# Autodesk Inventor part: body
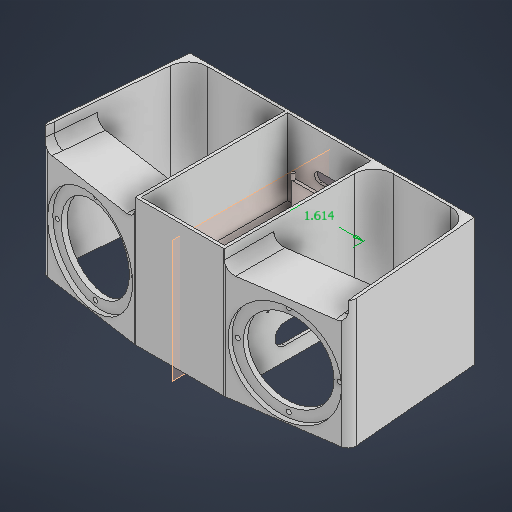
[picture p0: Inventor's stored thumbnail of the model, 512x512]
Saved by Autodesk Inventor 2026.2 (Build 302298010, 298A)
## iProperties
Created: 2026-08
Part Number: body
Material: Generic
Document SubType Name: Modeling
Designer: cpEwe
Density: 1 g/cm^3
Appearance: Default
Author: cpEwe
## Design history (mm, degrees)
sketch "Sketch1"
  geometry: L1 (-17.25, 41.25)-(17.25, 41.25); L2 (17.25, 41.25)-(17.25, -41.25); L3 (17.25, -41.25)-(-17.25, -41.25); L4 (-17.25, -41.25)-(-17.25, 41.25); L5 (-17.25, 41.25)-(17.25, -41.25); L6 (17.25, 41.25)-(-17.25, -41.25); C1 r 1 at (17.25, 41.25); C2 r 1 at (17.25, -41.25); C3 r 1 at (-17.25, -41.25); C4 r 1 at (-17.25, 41.25); 1 further point
  constraints: 12 end point, 4 centre point, 4 coincident, 3 equal radius, 2 midpoint, 2 parallel, 1 horizontal, 1 perpendicular
  dimensions: "d0" = 82.5 distance of L1.end L2.end; "d1" = 34.5 distance of L2.end L3.end; "d2" = 2 diameter of C1
extrude "Extrusion1" new body sketch "Sketch1" distance "d3" = 25; taper "d4" = 0 deg
sketch "Sketch2"
  geometry: L1 (0, 0)-(34.5, 0); L2 (34.5, 0)-(34.5, -82.5); L3 (34.5, -82.5)-(0, -82.5); L4 (36, -47.65)-(36, -82.65); L5 (36, -82.65)-(-1.5, -82.65); L6 (-1.5, -82.65)-(-1.5, -47.65); L7 (-1.5, -47.65)-(36, -47.65); L8 (36, -47.65)-(-1.5, -82.65); L9 (36, -82.65)-(-1.5, -47.65); L10 (0, -82.5)-(0, 0); C1 r 1 at (0, 0) reference; C2 r 1 at (34.5, -82.5) reference; C3 r 1 at (-1.5, -82.65); C4 r 1 at (-1.5, -47.65); C5 r 1 at (36, -47.65); C6 r 1 at (36, -82.65); 2 further points
  constraints: 20 end point, 4 centre point, 4 coincident, 3 equal radius, 3 parallel, 3 perpendicular, 2 midpoint, 1 horizontal
  dimensions: "d5" = 35 distance of L5.end L6.end; "d6" = 37.5 distance of L6.end L4.start; "d7" = 2 diameter of C3
extrude "Extrusion2" join sketch "Sketch2" distance "d8" = 7; taper "d9" = 0 deg
sketch "Sketch5"
  geometry: L1 (-9.75, 88.75)-(44.25, 88.75); L2 (44.25, 88.75)-(44.25, -6.25); L3 (44.25, -6.25)-(-9.75, -6.25); L4 (-9.75, -6.25)-(-9.75, 88.75); L5 (-9.75, 88.75)-(44.25, -6.25); L6 (44.25, 88.75)-(-9.75, -6.25); L7 (46.155, 90.655)-(-11.655, 90.655); L8 (-11.655, 90.655)-(-11.655, -8.155); L9 (-11.655, -8.155)-(46.155, -8.155); L10 (46.155, -8.155)-(46.155, 90.655); 1 further point
  constraints: 20 end point, 4 parallel, 2 midpoint, 2 perpendicular, 1 horizontal, 3 other
  dimensions: "d14" = 54 distance of L2.end L3.end; "d27" = 95 distance of L3.end L1.start; "d28" = 1.905 distance between parallel lines of L1 L7
extrude "Extrusion4" join sketch "Sketch5" stored distance "d16" = 2.54; taper "d17" = 0 deg
sketch "Sketch6"
  geometry: L1 (34.5, 0)-(0, 0); L2 (34.5, -1)-(0, -1); L3 (0, 1)-(34.5, 1); L4 (0, 82.5)-(34.5, 82.5); L5 (0, 83.5)-(34.5, 83.5); L6 (34.5, 81.5)-(0, 81.5); A1 r 1 centre (34.5, 0) between (34.5, -1) and (34.5, 1) reference; A2 r 1 centre (0, 0) between (0, -1) and (0, 1) reference; A3 r 1 centre (34.5, 0) between (34.5, -1) and (34.5, 1); A4 r 1 centre (0, 0) between (0, 1) and (0, -1); A5 r 1 centre (0, 82.5) between (0, 83.5) and (0, 81.5) reference; A6 r 1 centre (34.5, 82.5) between (34.5, 83.5) and (34.5, 81.5) reference; A7 r 1 centre (0, 82.5) between (0, 83.5) and (0, 81.5); A8 r 1 centre (34.5, 82.5) between (34.5, 81.5) and (34.5, 83.5); 3 further points
  constraints: 16 end point, 8 point on circle, 8 tangent, 4 centre point, 2 horizontal, 2 midpoint, 2 parallel
extrude "Extrusion5" join sketch "Sketch6" distance "d18" = 20; taper "d19" = 0 deg
sketch "Sketch7"
  geometry: L1 (36, -82.65)-(36, -47.65); L2 (35, -82.65)-(35, -47.65); L3 (37, -47.65)-(37, -82.65); L4 (-1.5, -82.65)-(-1.5, -47.65); L5 (-0.5, -82.65)-(-0.5, -47.65); L6 (-2.5, -47.65)-(-2.5, -82.65); A1 r 1 centre (36, -82.65) between (35, -82.65) and (37, -82.65) reference; A2 r 1 centre (36, -47.65) between (35, -47.65) and (37, -47.65) reference; A3 r 1 centre (36, -82.65) between (35, -82.65) and (37, -82.65); A4 r 1 centre (36, -47.65) between (37, -47.65) and (35, -47.65); A5 r 1 centre (-1.5, -82.65) between (-0.5, -82.65) and (-2.5, -82.65) reference; A6 r 1 centre (-1.5, -47.65) between (-0.5, -47.65) and (-2.5, -47.65) reference; A7 r 1 centre (-1.5, -82.65) between (-2.5, -82.65) and (-0.5, -82.65); A8 r 1 centre (-1.5, -47.65) between (-0.5, -47.65) and (-2.5, -47.65); 3 further points
  constraints: 16 end point, 8 point on circle, 8 tangent, 4 centre point, 2 midpoint, 2 parallel, 2 vertical
extrude "Extrusion6" join sketch "Sketch7" distance "d20" = 3; taper "d21" = 0 deg
sketch "Sketch9"
  geometry: L1 (37.75, -1.129)-(-3.25, -1.129); L2 (-3.25, -1.129)-(-3.25, 83.629); L3 (-3.25, 83.629)-(37.75, 83.629); L4 (37.75, 83.629)-(37.75, -1.129); L5 (37.75, -1.129)-(-3.25, 83.629); L6 (-3.25, -1.129)-(37.75, 83.629); 1 further point
  constraints: 12 end point, 2 midpoint, 2 parallel, 1 horizontal, 1 perpendicular
  dimensions: "d26" = 41 distance of L2.end L3.end
sketch "Sketch10"
  geometry: L1 (-11.655, 90.655)-(-11.655, -8.155) reference; L2 (-11.655, -8.155)-(46.155, -8.155) reference; L3 (46.155, -8.155)-(46.155, 90.655) reference; L4 (46.155, 90.655)-(-11.655, 90.655) reference; L5 (0, 83.5)-(34.5, 83.5) reference; L6 (34.5, 81.5)-(0, 81.5) reference; L7 (34.5, -1)-(0, -1) reference; L8 (0, 1)-(34.5, 1) reference; L9 (-9.75, -6.25)-(-9.75, 88.75); L10 (-9.75, 88.75)-(44.25, 88.75); L11 (44.25, 88.75)-(44.25, -6.25); L12 (44.25, -6.25)-(-9.75, -6.25); A1 r 1 centre (34.5, 82.5) between (34.5, 81.5) and (34.5, 83.5) reference; A2 r 1 centre (0, 82.5) between (0, 83.5) and (0, 81.5) reference; A3 r 1 centre (0, 0) between (0, 1) and (0, -1) reference; A4 r 1 centre (34.5, 0) between (34.5, -1) and (34.5, 1) reference; 1 further point
  constraints: 8 end point, 3 other
  dimensions: "d29" = 1.905 distance between parallel lines of L1 L9
extrude "Extrusion8" join sketch "Sketch10" stored distance "d30" = 67; taper "d31" = 0 deg
sketch "Sketch11"
  geometry: L1 (11.655, -13.5)-(46.155, -13.5) reference; L2 (22.555, -10.325)-(35.255, -10.325); L3 (12.655, -9.77)-(10.655, -9.77) reference; L4 (22.555, -13.5)-(35.255, -13.5); L5 (35.255, -7.15)-(22.555, -7.15); L6 (11.155, -39.04)-(28.905, -39.04); L7 (28.905, -39.04)-(28.905, -67); L8 (1.905, -67)-(55.905, -67) reference; L9 (22.405, -39.04)-(34.405, -39.04); L10 (34.405, -39.04)-(34.405, -53.04); L11 (34.405, -53.04)-(22.405, -53.04); L12 (22.405, -53.04)-(22.405, -39.04); A1 r 3.175 centre (22.555, -10.325) between (22.555, -7.15) and (22.555, -13.5); A2 r 3.175 centre (35.255, -10.325) between (35.255, -13.5) and (35.255, -7.15); 6 further points
  constraints: 20 end point, 4 parallel, 4 point on circle, 4 tangent, 2 centre point, 2 horizontal, 2 midpoint, 1 collinear, 1 perpendicular, 1 point on line
  dimensions: "d32" = 12.7 distance of L5.start L5.end; "d33" = 3.175 radius of A2; "d41" = 12 distance of L10.end L11.end; "d42" = 14 distance of L11.end L9.start; "d43" = 6.5 distance between parallel lines of L12 L7
extrude "Extrusion9" cut sketch "Sketch11" distance "d34" = 67; taper "d35" = 0 deg
chamfer "Chamfer1" distance "d44" = 1.905; stored, may be unused: second distance "d45" = 3.175, angle "d46" = 45 deg
fillet "Fillet2" dims "d47" = 3.175
sketch "Sketch12"
  geometry: L1 (114.784, -8.12)-(107.729, -88.75); L2 (117.227, -2.055)-(109.475, -90.655); L3 (-11.655, -90.655)-(46.155, -90.655) reference; L4 (3.338, -90.655)-(40.307, -90.655); L5 (61.148, -90.655)-(109.475, -90.655); L6 (46.155, -88.75)-(107.729, -88.75); L7 (46.155, -90.655)-(46.155, 8.155) reference; L8 (46.155, -90.656)-(61.148, -90.655); L9 (46.155, 8.155)-(117.227, -2.055); L10 (114.784, -8.12)-(45.879, 1.779); L11 (46.155, 8.155)-(45.879, 1.779); L12 (46.155, -88.75)-(46.155, -90.656); L13 (46.155, -94.045)-(44.349, -93.887); L14 (46.155, 8.155)-(46.155, -90.655) reference; 4 further points
  constraints: 22 end point, 3 collinear, 2 parallel, 1 point on line
  dimensions: "d55" = 1.905 distance between parallel lines of L1 L2; "d56" = 1.905 distance between parallel lines of L5 L6; "d92" = 6.35 distance between parallel lines of L9 L10; "d93" = 68.62873 distance from line of L14 L1.start
extrude "Extrusion10" join sketch "Sketch12" distance "d57" = 67; taper "d58" = 0 deg
workplane "Work Plane1"
sketch "Sketch14"
  geometry: L1 (15.133, 0)-(-56.668, 0) reference; L2 (-56.668, 0)-(12.515, 66.639); C1 r 32.5 at (-22.077, 33.319); 1 further point
  constraints: 2 end point, 1 centre point, 1 midpoint
  dimensions: "d63" = 65 diameter of C1
extrude "Extrusion12" cut sketch "Sketch14" distance "d64" = 3; taper "d65" = 0 deg
sketch "Sketch15"
  geometry: C1 r 26 at (0, 0); 1 further point
  constraints: 1 centre point
  dimensions: "d66" = 52 diameter of C1
extrude "Extrusion13" cut sketch "Sketch15" distance "d67" = 9.34999; taper "d68" = 0 deg
sketch "Sketch16"
  geometry: L1 (8.89, 8.89)-(8.89, 22.07); L2 (8.89, 22.07)-(86.11, 22.07); L3 (86.11, 22.07)-(86.11, 8.89); L4 (86.11, 8.89)-(8.89, 8.89); L5 (47.5, 8.89)-(47.5, 22.07); L6 (63.982, 8.89)-(31.018, 8.89); L7 (31.018, 8.89)-(31.018, 22.07); L8 (31.018, 22.07)-(63.982, 22.07); L9 (63.982, 22.07)-(63.982, 8.89); L10 (63.982, 8.89)-(31.018, 22.07); L11 (31.018, 8.89)-(63.982, 22.07); 5 further points
  constraints: 22 end point, 5 midpoint, 2 parallel, 1 horizontal, 1 perpendicular, 1 point on line
extrude "Extrusion14" cut sketch "Sketch16" stored distance "d70" = 103.01249; taper "d71" = 0 deg
mirror "Mirror2"
fillet "Fillet3" dims "d72" = 6.35
fillet "Fillet4" dims "d73" = 12.7
sketch "Sketch20"
  geometry: C1 r 1.5 at (0, 29.181); C2 r 1.5 at (-29.181, 0); C3 r 1.5 at (0, -29.181); C4 r 1.5 at (29.181, 0); A1 r 26 centre (0, 0) between (-13.601, 22.159) and (26, 0) reference; 4 further points; 1 other entity
  constraints: 4 centre point, 10 other
  dimensions: "d77" = 3 diameter of C1; "d78" = 29 dimension on C1.centre; "d81" = 360 deg dimension on A1.centre C1.centre (derived)
extrude "Extrusion16" cut sketch "Sketch20" distance "d83" = 25.4; taper "d84" = 0 deg
mirror "Mirror3"
sketch "Sketch25"
  geometry: L1 (-11.655, 88.75)-(-11.655, -1.74) reference; L2 (-80.284, 8.12)-(-11.655, -1.74) reference; L3 (-74.244, 77.157)-(-80.284, 8.12) reference; L4 (-11.655, 88.75)-(-61.592, 88.75) reference; L5 (-11.655, 90.656)-(-11.655, 90.655) reference; L6 (-26.648, 90.655)-(-11.655, 90.656) reference; L7 (-74.975, 90.655)-(-26.648, 90.655) reference; L8 (-82.727, 2.055)-(-74.975, 90.655) reference; L9 (-11.655, -8.155)-(-82.727, 2.055) reference; L10 (-11.655, -8.155)-(46.155, -8.155) reference; L11 (46.155, -8.155)-(117.227, 2.055) reference; L12 (117.227, 2.055)-(109.475, 90.655) reference; L13 (109.475, 90.655)-(61.148, 90.655) reference; L14 (61.148, 90.655)-(46.155, 90.656) reference; L15 (46.155, 90.656)-(46.155, 90.655) reference; L16 (46.155, 90.655)-(-11.655, 90.655) reference; L17 (58.855, 88.75)-(96.092, 88.75) reference; L18 (108.744, 77.157)-(114.784, 8.12) reference; L19 (114.784, 8.12)-(46.155, -1.74) reference; L20 (46.155, -1.74)-(46.155, 76.05) reference; L21 (-9.75, -6.25)-(-9.75, 88.75) reference; L22 (-9.75, 88.75)-(44.25, 88.75) reference; L23 (44.25, 88.75)-(44.25, -6.25) reference; L24 (44.25, -6.25)-(-9.75, -6.25) reference; L25 (-74.244, 77.157)-(-80.284, 8.12) reference; L26 (-78.067, 33.462)-(-11.655, 23.921); L27 (17.25, 111.287)-(17.25, -28.062) reference; L28 (112.567, 33.462)-(46.155, 23.921); A1 r 12.7 centre (-61.592, 76.05) between (-61.592, 88.75) and (-74.244, 77.157) reference; A2 r 12.7 centre (96.092, 76.05) between (108.744, 77.157) and (96.092, 88.75) reference; A3 r 12.7 centre (58.855, 76.05) between (58.855, 88.75) and (46.155, 76.05) reference; 4 further points
  constraints: 4 end point, 2 point on line, 2 symmetric about line, 1 parallel
  dimensions: "d94" = 25.4 distance between parallel lines of L2 L26
extrude "Extrusion20" join sketch "Sketch25" distance "d95" = 3.175; taper "d96" = 0 deg
sketch "Sketch26"
  geometry: L1 (-11.655, 90.655)-(46.155, 90.655) reference; L2 (46.155, 90.655)-(46.155, 90.656) reference; L3 (46.155, 90.656)-(61.148, 90.655) reference; L4 (61.148, 90.655)-(109.475, 90.655) reference; L5 (109.475, 90.655)-(117.227, 2.055) reference; L6 (117.227, 2.055)-(46.155, -8.155) reference; L7 (46.155, -8.155)-(-11.655, -8.155) reference; L8 (-82.727, 2.055)-(-11.655, -8.155) reference; L9 (-74.975, 90.655)-(-82.727, 2.055) reference; L10 (-26.648, 90.655)-(-74.975, 90.655) reference; L11 (-11.655, 90.656)-(-26.648, 90.655) reference; L12 (-11.655, 90.655)-(-11.655, 90.656) reference; L13 (46.155, 76.05)-(46.155, -1.74) reference; L14 (46.155, -1.74)-(114.784, 8.12) reference; L15 (114.784, 8.12)-(108.744, 77.157) reference; L16 (96.092, 88.75)-(58.855, 88.75) reference; L17 (-80.284, 8.12)-(-74.244, 77.157) reference; L18 (-11.655, -1.74)-(-80.284, 8.12) reference; L19 (-11.655, -1.74)-(-11.655, 88.75) reference; L20 (-61.592, 88.75)-(-11.655, 88.75) reference; L21 (-9.75, 88.75)-(-9.75, -6.25) reference; L22 (-9.75, -6.25)-(44.25, -6.25) reference; L23 (44.25, -6.25)-(44.25, 88.75) reference; L24 (44.25, 88.75)-(-9.75, 88.75) reference; L25 (114.784, 8.12)-(115.687, 1.834); L26 (46.155, -8.155)-(117.227, 2.055) reference; L27 (46.155, 76.05)-(46.155, -1.74) reference; L28 (46.155, -1.74)-(46.155, -8.155); L29 (17.25, 111.287)-(17.25, -28.062) reference; L30 (-80.284, 8.12)-(-81.187, 1.834); L31 (-11.655, -1.74)-(-11.655, -8.155); A1 r 12.7 centre (96.092, 76.05) between (108.744, 77.157) and (96.092, 88.75) reference; A2 r 12.7 centre (58.855, 76.05) between (58.855, 88.75) and (46.155, 76.05) reference; A3 r 12.7 centre (-61.592, 76.05) between (-61.592, 88.75) and (-74.244, 77.157) reference; 3 further points
  constraints: 8 end point, 1 collinear, 1 perpendicular, 1 point on line, 1 symmetric about line
extrude "Extrusion21" join sketch "Sketch26" distance "d97" = 12.7; taper "d98" = 0 deg
fillet "Fillet6" dims "d99" = 5.08
fillet "Fillet7" dims "d100" = 6.35
body "Solid1"
node "Projected Loop2"
node "Sketch Circular Pattern1" dims "d81" = 360 deg (derived)
node "Projected Loop10"
node "Projected Loop11"
